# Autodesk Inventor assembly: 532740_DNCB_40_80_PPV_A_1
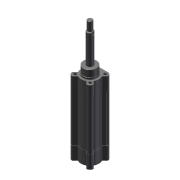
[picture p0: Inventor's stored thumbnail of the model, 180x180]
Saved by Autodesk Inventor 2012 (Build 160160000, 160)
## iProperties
Company: CAD-Verlag
Created: 2004-09
Part Number: 532740_DNCB_40_80_PPV_A_1
Document SubType Name: Assembly
Designer: Greiling
Manufacturer: Standard
Standards Organization: Custom
Checked By: Jürgen Kronas
Stock Number: 10-10012
Author: Juergen Kronas
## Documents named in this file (3)
- C:\DemoDaten2012\CAD Daten\Daten Vault 2012 Inventor\Kapitel 4\Anschlag\532740_DNCB_40_80_PPV_A_1.iam
- C:\DemoDaten2012\CAD Daten\Daten Vault 2012 Inventor\Kapitel 4\Anschlag\1.ipt
- C:\DemoDaten2012\CAD Daten\Daten Vault 2012 Inventor\Kapitel 4\Anschlag\2.ipt
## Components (2 placed, 2 different names)
1. 1 — Passend:1, Abstand
2. 2 — Passend:1, Abstand
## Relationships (2: Mate 1, Flush 1)
- Passend:1 [Mate]: 1 ↔ 2
- Abstand [Flush]: 1 ↔ 2
